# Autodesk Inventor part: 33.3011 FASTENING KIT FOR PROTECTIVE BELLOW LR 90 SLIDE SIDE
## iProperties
Created: 2007-06
Part Number: 33.3011 FASTENING KIT FOR PROTECTIVE BELLOW LR 90 SLIDE SIDE
Document SubType Name: Modeling
Designer: Andy Moles
Material: Aluminum-6061
Mass: 158.78 g
Surface Area: 421.094 cm^2
Volume: 58.5903 cm^3
Density: 2.71 g/cm^3
Author: Andy Moles
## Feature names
1. Extrusion1
2. Hole1
